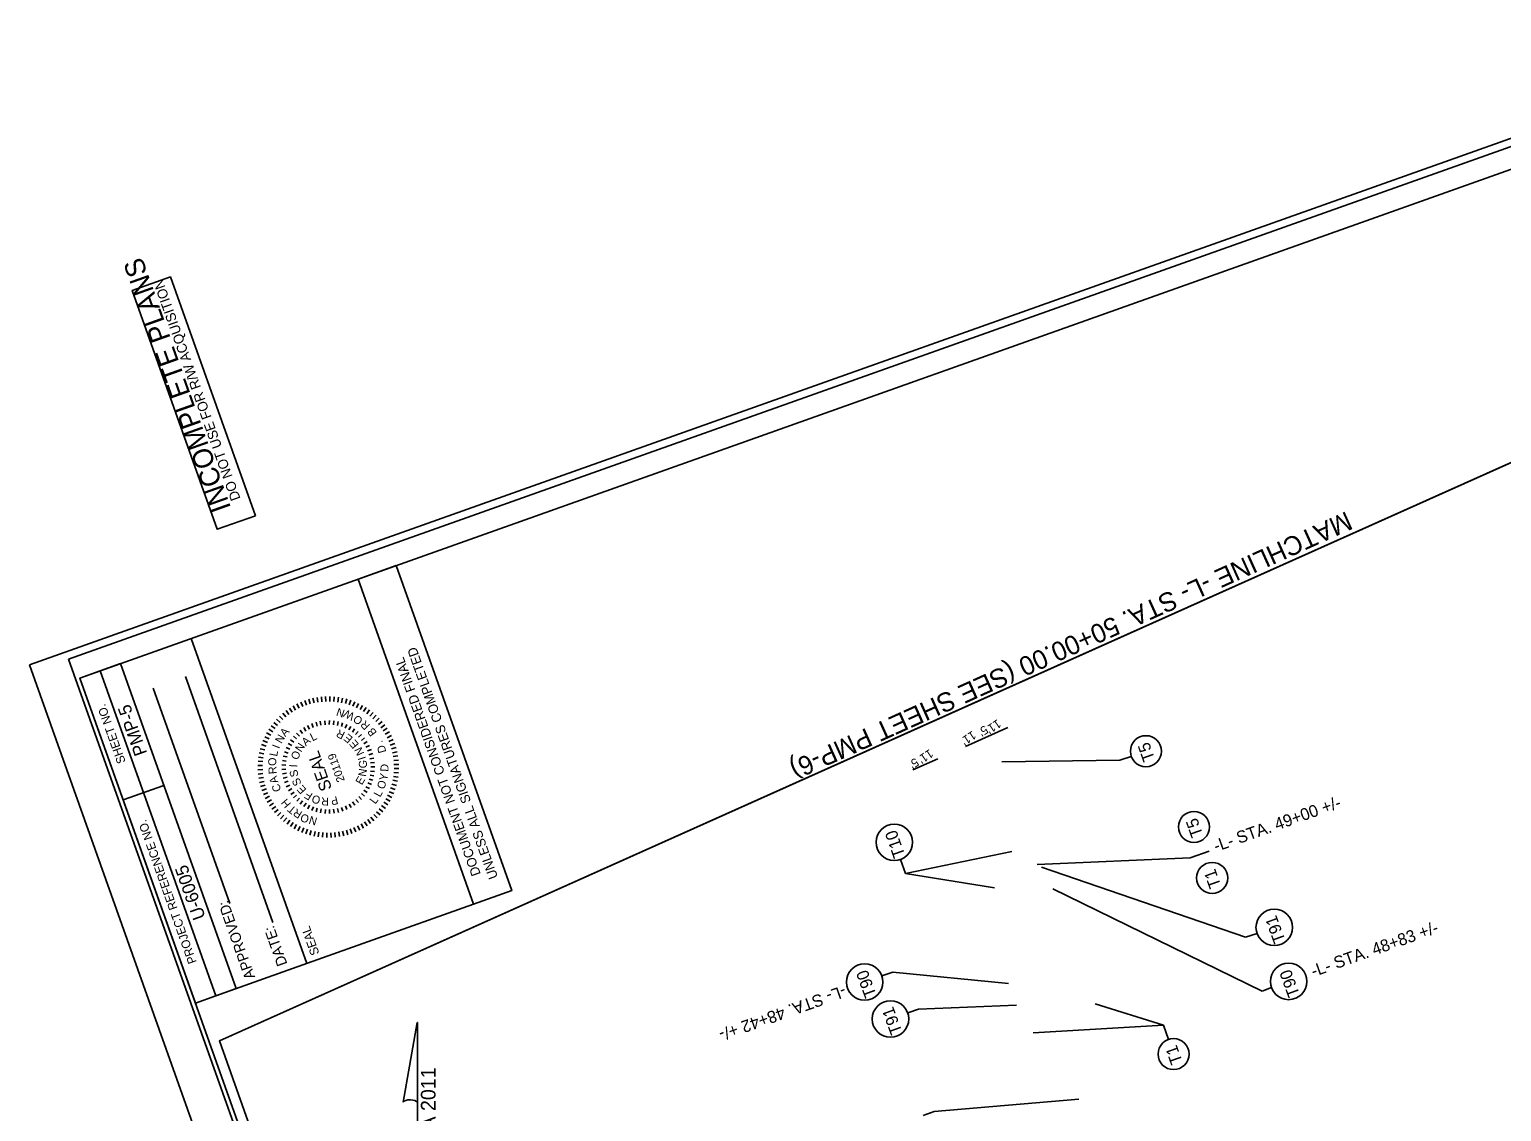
# Model space of a CAD drawing. Extents: x 1615843 to 1617934, y 901966 to 903921.
# Drawn here: x 1615843 to 1616697, y 903293 to 903921 of the extents above; entities that cross this region are included whole.
import ezdxf

# ---------------------------------------------------------------- set-up
doc = ezdxf.new("R2010")
doc.units = 0
for name, color, linetype in [('Matchline', 7, 'Continuous'), ('Matchline Text', 7, 'Continuous'), ('Prop Terminator CELL', 7, 'Continuous'), ('Scratch_Level_0', 7, 'Continuous'), ('Sheet Block Revision CELL', 7, 'Continuous'), ('Sheet Border Standard 30in CELL', 7, 'Continuous'), ('Sheet Clip Boundary CELL', 7, 'Continuous'), ('Sheet Data Field CELL', 7, 'Continuous'), ('Sheet North Arrow Point CELL', 7, 'Continuous'), ('Sheet Plan Layout CELL', 7, 'Continuous'), ('Sheet Plot Border Inside CELL', 7, 'Continuous'), ('Sheet Plot Border Outside CELL', 7, 'Continuous'), ('Sheet Sticker Exception Certification CELL', 7, 'Continuous'), ('Sheet Sticker Incomplete CELL', 7, 'Continuous'), ('Sheet Sticker Preliminary CELL', 7, 'Continuous')]:
    doc.layers.add(name, color=color, linetype=linetype)

msp = doc.modelspace()

# ---------------------------------------------------------------- linework, layer by layer
at = {"layer": 'Matchline'}
msp.add_line((1615953.12, 903334.31), (1616903.33, 903759.78), dxfattribs=at)
at = {"layer": 'Prop Terminator CELL'}
for p, q in [((1616059.69, 903298.71), (1616067.89, 903345.06)), ((1616067.94, 903345.06), (1616067.89, 903345.06)), ((1616067.94, 903345.06), (1616067.89, 903345.06)), ((1616067.94, 903345.06), (1616067.94, 903297.26)), ((1616067.94, 903272.46), (1616067.94, 903298.66)), ((1616067.94, 903297.26), (1616067.94, 903298.61))]:
    msp.add_line(p, q, dxfattribs=at)
msp.add_ellipse((1616063.83, 903298.22), major_axis=(4.23, -0.03), ratio=0.461098, start_param=0.216388, end_param=2.908219, dxfattribs=at)
at = {"layer": 'Sheet Block Revision CELL'}
for p, q in [((1616002.65, 903531.64), (1616003.58, 903529.02)), ((1616005.01, 903532.4), (1616005.78, 903529.72)), ((1616007.4, 903533.01), (1616008.01, 903530.29)), ((1616009.82, 903533.48), (1616010.26, 903530.73)), ((1616012.27, 903533.79), (1616012.55, 903531.02)), ((1616014.73, 903533.96), (1616014.84, 903531.18)), ((1616017.2, 903533.98), (1616017.14, 903531.2)), ((1616019.67, 903533.85), (1616019.44, 903531.08)), ((1616022.12, 903533.58), (1616021.72, 903530.82)), ((1616024.56, 903533.15), (1616023.99, 903530.42)), ((1616026.96, 903532.58), (1616026.23, 903529.89)), ((1616029.32, 903531.87), (1616028.43, 903529.23)), ((1616031.64, 903531.01), (1616030.59, 903528.43)), ((1615988.05, 903522.64), (1615989.97, 903520.63)), ((1615989.88, 903524.3), (1615991.68, 903522.17)), ((1615991.81, 903525.84), (1615993.48, 903523.6)), ((1615993.83, 903527.26), (1615995.36, 903524.93)), ((1615995.93, 903528.55), (1615997.32, 903526.14)), ((1615998.11, 903529.71), (1615999.35, 903527.22)), ((1616000.35, 903530.75), (1616001.44, 903528.18)), ((1616033.89, 903530.01), (1616032.7, 903527.5)), ((1616036.09, 903528.89), (1616034.74, 903526.45)), ((1616038.22, 903527.63), (1616036.72, 903525.28)), ((1616040.26, 903526.24), (1616038.63, 903523.98)), ((1616042.21, 903524.74), (1616040.45, 903522.58)), ((1616044.08, 903523.11), (1616042.18, 903521.07)), ((1615981.8, 903515.02), (1615984.15, 903513.53)), ((1615983.18, 903517.07), (1615985.44, 903515.44)), ((1615984.69, 903519.02), (1615986.85, 903517.26)), ((1615986.31, 903520.89), (1615988.36, 903518.99)), ((1615999.9, 903514.48), (1616001.32, 903512.64)), ((1616002.04, 903515.97), (1616003.27, 903514)), ((1616004.31, 903517.24), (1616005.34, 903515.16)), ((1616006.7, 903518.29), (1616007.53, 903516.12)), ((1616009.17, 903519.09), (1616009.79, 903516.86)), ((1616012.03, 903517.36), (1616011.63, 903519.65)), ((1616014.3, 903519.98), (1616014.47, 903517.67)), ((1616016.9, 903520.05), (1616016.85, 903517.73)), ((1616019.49, 903519.87), (1616019.22, 903517.56)), ((1616022.06, 903519.44), (1616021.57, 903517.17)), ((1616024.58, 903518.76), (1616023.86, 903516.55)), ((1616027.01, 903517.84), (1616026.09, 903515.71)), ((1616029.34, 903516.69), (1616028.22, 903514.66)), ((1616031.56, 903515.32), (1616030.25, 903513.41)), ((1616045.83, 903521.38), (1616043.82, 903519.46)), ((1616047.49, 903519.55), (1616045.36, 903517.74)), ((1616049.03, 903517.62), (1616046.8, 903515.95)), ((1616050.45, 903515.6), (1616048.12, 903514.07)), ((1615977.56, 903506.12), (1615980.2, 903505.24)), ((1615978.42, 903508.44), (1615981, 903507.4)), ((1615979.41, 903510.7), (1615981.92, 903509.5)), ((1615980.54, 903512.9), (1615982.98, 903511.55)), ((1615993.06, 903506.72), (1615995.06, 903505.55)), ((1615994.47, 903508.9), (1615996.36, 903507.54)), ((1615996.1, 903510.93), (1615997.85, 903509.4)), ((1615997.92, 903512.8), (1615999.5, 903511.11)), ((1616033.63, 903513.75), (1616032.14, 903511.97)), ((1616035.54, 903511.98), (1616033.88, 903510.35)), ((1616037.28, 903510.03), (1616035.47, 903508.57)), ((1616038.81, 903507.93), (1616036.87, 903506.65)), ((1616040.13, 903505.69), (1616038.08, 903504.61)), ((1616051.74, 903513.49), (1616049.33, 903512.11)), ((1616052.91, 903511.32), (1616050.41, 903510.08)), ((1616053.94, 903509.08), (1616051.38, 903507.99)), ((1616054.84, 903506.77), (1616052.21, 903505.84)), ((1615975.85, 903498.93), (1615978.61, 903498.53)), ((1615976.27, 903501.36), (1615979, 903500.8)), ((1615976.84, 903503.76), (1615979.53, 903503.04)), ((1615989.64, 903496.95), (1615991.94, 903496.62)), ((1615990.14, 903499.5), (1615992.39, 903498.95)), ((1615990.87, 903502), (1615993.07, 903501.23)), ((1615991.85, 903504.41), (1615993.96, 903503.44)), ((1616041.24, 903503.33), (1616039.09, 903502.46)), ((1616042.11, 903500.88), (1616039.88, 903500.21)), ((1616042.73, 903498.36), (1616040.46, 903497.9)), ((1616055.59, 903504.42), (1616052.91, 903503.65)), ((1616056.2, 903502.03), (1616053.48, 903501.42)), ((1616056.67, 903499.61), (1616053.92, 903499.16)), ((1616056.99, 903497.16), (1616054.21, 903496.88)), ((1615975.44, 903494.01), (1615978.23, 903493.95)), ((1615975.46, 903491.54), (1615978.25, 903491.65)), ((1615975.58, 903496.47), (1615978.35, 903496.25)), ((1615975.63, 903489.07), (1615978.4, 903489.35)), ((1615989.4, 903494.36), (1615991.72, 903494.25)), ((1615989.4, 903491.75), (1615991.72, 903491.87)), ((1615989.66, 903489.16), (1615991.96, 903489.51)), ((1616042.76, 903488), (1616040.48, 903488.44)), ((1616040.81, 903495.54), (1616043.12, 903495.76)), ((1616043.13, 903490.58), (1616040.81, 903490.8)), ((1616043.25, 903493.18), (1616040.92, 903493.18)), ((1616057.04, 903489.76), (1616054.27, 903489.99)), ((1616057.16, 903494.69), (1616054.37, 903494.58)), ((1616057.18, 903492.23), (1616054.39, 903492.29)), ((1615975.95, 903486.63), (1615978.7, 903487.07)), ((1615976.42, 903484.21), (1615979.13, 903484.81)), ((1615977.03, 903481.81), (1615979.7, 903482.58)), ((1615977.78, 903479.46), (1615980.41, 903480.39)), ((1615990.17, 903486.61), (1615992.42, 903487.17)), ((1615990.92, 903484.12), (1615993.1, 903484.89)), ((1615993.1, 903484.89), (1615990.92, 903484.12)), ((1615991.91, 903481.71), (1615994.01, 903482.69)), ((1615993.12, 903479.41), (1615995.12, 903480.59)), ((1616038.88, 903478.41), (1616036.93, 903479.68)), ((1616040.19, 903480.65), (1616038.14, 903481.73)), ((1616041.28, 903483.01), (1616039.13, 903483.89)), ((1616042.14, 903485.47), (1616039.92, 903486.13)), ((1616055.06, 903480.11), (1616052.42, 903480.99)), ((1616055.77, 903482.47), (1616053.09, 903483.2)), ((1616056.35, 903484.87), (1616053.62, 903485.44)), ((1616056.77, 903487.31), (1616054.01, 903487.7)), ((1615978.68, 903477.16), (1615981.24, 903478.24)), ((1615979.71, 903474.92), (1615982.2, 903476.15)), ((1615980.87, 903472.74), (1615983.29, 903474.13)), ((1615982.17, 903470.64), (1615984.5, 903472.17)), ((1615994.55, 903477.23), (1615996.43, 903478.6)), ((1615996.18, 903475.2), (1615997.92, 903476.75)), ((1615998.01, 903473.35), (1615999.59, 903475.05)), ((1616000, 903471.67), (1616001.41, 903473.52)), ((1616002.15, 903470.2), (1616003.37, 903472.18)), ((1616029.46, 903469.6), (1616028.32, 903471.63)), ((1616031.67, 903470.98), (1616030.34, 903472.89)), ((1616033.73, 903472.57), (1616032.23, 903474.34)), ((1616035.63, 903474.35), (1616033.96, 903475.96)), ((1616037.35, 903476.29), (1616035.54, 903477.75)), ((1616050.82, 903471.21), (1616048.47, 903472.7)), ((1616052.08, 903473.34), (1616049.64, 903474.68)), ((1616053.21, 903475.53), (1616050.69, 903476.73)), ((1616054.2, 903477.79), (1616051.62, 903478.84)), ((1615983.59, 903468.61), (1615985.82, 903470.29)), ((1615985.13, 903466.69), (1615987.25, 903468.49)), ((1615986.78, 903464.85), (1615988.8, 903466.78)), ((1615988.54, 903463.12), (1615990.43, 903465.17)), ((1615990.4, 903461.5), (1615992.17, 903463.65)), ((1616004.43, 903468.94), (1616005.45, 903471.03)), ((1616006.81, 903467.91), (1616007.63, 903470.08)), ((1616009.29, 903467.1), (1616009.9, 903469.35)), ((1616011.83, 903466.55), (1616012.22, 903468.84)), ((1616014.42, 903466.24), (1616014.58, 903468.56)), ((1616017.02, 903466.19), (1616016.96, 903468.51)), ((1616019.62, 903466.38), (1616019.33, 903468.69)), ((1616022.18, 903466.83), (1616021.68, 903469.09)), ((1616024.69, 903467.51), (1616023.97, 903469.72)), ((1616027.13, 903468.44), (1616026.2, 903470.57)), ((1616040.81, 903460.4), (1616039.14, 903462.63)), ((1616042.74, 903461.93), (1616040.94, 903464.06)), ((1616044.57, 903463.59), (1616042.65, 903465.6)), ((1616046.31, 903465.35), (1616044.26, 903467.24)), ((1616047.93, 903467.21), (1616045.77, 903468.98)), ((1616049.43, 903469.17), (1616047.18, 903470.8)), ((1615992.36, 903459.99), (1615993.99, 903462.25)), ((1615994.4, 903458.61), (1615995.9, 903460.96)), ((1615996.53, 903457.35), (1615997.88, 903459.78)), ((1615998.72, 903456.22), (1615999.92, 903458.73)), ((1616000.98, 903455.22), (1616002.03, 903457.81)), ((1616003.3, 903454.37), (1616004.19, 903457.01)), ((1616005.66, 903453.65), (1616006.39, 903456.34)), ((1616008.06, 903453.08), (1616008.63, 903455.81)), ((1616010.5, 903452.66), (1616010.89, 903455.42)), ((1616012.95, 903452.38), (1616013.18, 903455.16)), ((1616015.42, 903452.25), (1616015.48, 903455.04)), ((1616017.88, 903452.27), (1616017.77, 903455.06)), ((1616020.35, 903452.44), (1616020.07, 903455.21)), ((1616022.8, 903452.76), (1616022.35, 903455.51)), ((1616025.22, 903453.23), (1616024.61, 903455.94)), ((1616027.61, 903453.84), (1616026.84, 903456.51)), ((1616029.97, 903454.59), (1616029.03, 903457.22)), ((1616032.27, 903455.49), (1616031.18, 903458.05)), ((1616034.51, 903456.52), (1616033.27, 903459.01)), ((1616036.69, 903457.68), (1616035.3, 903460.1)), ((1616038.79, 903458.98), (1616037.26, 903461.3))]:
    msp.add_line(p, q, dxfattribs=at)
at = {"layer": 'Sheet Border Standard 30in CELL'}
for p, q in [((1615951.11, 903360.45), (1615884.09, 903548.94)), ((1615962.88, 903364.63), (1615895.87, 903553.13)), ((1615962.88, 903364.63), (1615895.87, 903553.13)), ((1615897.44, 903474.09), (1615921, 903482.46))]:
    msp.add_line(p, q, dxfattribs=at)
for points in [[(1615872.27, 903544.74), (1616374.72, 902131.39), (1617364.06, 902483.11), (1616861.61, 903896.45)], [(1615939.28, 903356.24), (1615872.27, 903544.74), (1615895.87, 903553.13), (1615962.88, 903364.63)]]:
    msp.add_lwpolyline(points, close=True, dxfattribs=at)
at = {"layer": 'Sheet Clip Boundary CELL'}
for p, q in [((1616410.35, 903516.09), (1616385.7, 903505.08)), ((1616369.73, 903497.94), (1616355.12, 903491.41)), ((1616406.85, 903496.18), (1616475.15, 903497.09)), ((1616475.15, 903497.09), (1616481.82, 903499.29)), ((1616347.97, 903439.52), (1616350.88, 903431.32)), ((1616412.63, 903444.14), (1616350.88, 903431.32)), ((1616412.63, 903444.14), (1616350.88, 903431.32)), ((1616427.35, 903436.64), (1616515.95, 903440.41)), ((1616526.9, 903444.3), (1616515.95, 903440.41)), ((1616402.58, 903423.11), (1616350.88, 903431.32)), ((1616429.84, 903435), (1616548.07, 903394.39)), ((1616436.29, 903422.47), (1616557.64, 903363.25)), ((1616548.07, 903394.39), (1616554.75, 903396.59)), ((1616343.54, 903374.23), (1616337.21, 903371.98)), ((1616410.71, 903367.51), (1616343.54, 903374.23)), ((1616557.64, 903363.25), (1616563.09, 903365.25)), ((1616358.52, 903352.81), (1616352.19, 903350.56)), ((1616415.35, 903355.12), (1616358.52, 903352.81)), ((1616460.8, 903355.84), (1616500.42, 903343.37)), ((1616424.97, 903338.99), (1616500.42, 903343.37)), ((1616503.34, 903335.18), (1616500.42, 903343.37)), ((1616451.42, 903300.58), (1616367.56, 903293.34)), ((1616367.56, 903293.34), (1616361.23, 903291.09))]:
    msp.add_line(p, q, dxfattribs=at)
for centre, radius in [((1616490.31, 903502.3), 9.01), ((1616518.19, 903458.36), 9.01), ((1616344.43, 903449.48), 10.58), ((1616528.71, 903428.79), 9.01), ((1616564.72, 903400.14), 10.58), ((1616327.25, 903368.43), 10.58), ((1616573.06, 903368.79), 10.58), ((1616342.22, 903347.02), 10.58), ((1616506.35, 903326.69), 9.01)]:
    msp.add_circle(centre, radius, dxfattribs=at)
at = {"layer": 'Sheet North Arrow Point CELL'}
for p, q in [((1616033.51, 903602.06), (1616100.52, 903413.57)), ((1616003.8, 903379.18), (1615936.79, 903567.67)), ((1616100.52, 903413.57), (1615995.56, 903376.25)), ((1615995.56, 903376.25), (1615951.11, 903360.45))]:
    msp.add_line(p, q, dxfattribs=at)
at = {"layer": 'Sheet Plan Layout CELL'}
for p, q in [((1615984.13, 903402.97), (1615933.46, 903545.53)), ((1615959.12, 903413.91), (1615914.7, 903538.86))]:
    msp.add_line(p, q, dxfattribs=at)
at = {"layer": 'Sheet Plot Border Inside CELL'}
msp.add_lwpolyline([(1615865.68, 903555.66), (1616423.91, 901985.43), (1617418.05, 902338.86), (1616859.83, 903909.09)], close=True, dxfattribs=at)
at = {"layer": 'Sheet Plot Border Outside CELL'}
msp.add_lwpolyline([(1615843.02, 903552.38), (1616407.11, 901965.67), (1617443.56, 902334.13), (1616879.47, 903920.85)], close=True, dxfattribs=at)
at = {"layer": 'Sheet Sticker Exception Certification CELL'}
msp.add_lwpolyline([(1616100.52, 903413.57), (1616033.51, 903602.06), (1616055.65, 903609.93), (1616122.66, 903421.44)], close=True, dxfattribs=at)
at = {"layer": 'Sheet Sticker Incomplete CELL'}
msp.add_lwpolyline([(1616920.55, 902382.99), (1616299.46, 902356.07), (1615953.12, 903334.31), (1616369.18, 903520.6), (1616903.33, 903759.78), (1617120.19, 903154.34), (1616822.61, 903059.96), (1617083.45, 902390.05)], close=True, dxfattribs=at)
at = {"layer": 'Sheet Sticker Preliminary CELL'}
msp.add_lwpolyline([(1615974.04, 903638.86), (1615951.9, 903630.98), (1615902.66, 903769.49), (1615924.8, 903777.36)], close=True, dxfattribs=at)

# ---------------------------------------------------------------- texts
at = {"layer": 'Matchline Text'}
msp.add_text('MATCHLINE -L- STA. 50+00.00 (SEE SHEET PMP-6)', height=11, rotation=204.28176, dxfattribs=at).set_placement((1616606.6, 903641.67))
at = {"layer": 'Prop Terminator CELL'}
msp.add_text('NAD 83/NA 2011', height=8.5, rotation=90, dxfattribs=at).set_placement((1616078.46, 903231.75))
at = {"layer": 'Scratch_Level_0'}
for s, p in [('APPROVED:', (1615973.98, 903371.32)), ('DATE:', (1615992.65, 903378.94))]:
    msp.add_text(s, height=6.11, rotation=109.56562, dxfattribs=at).set_placement(p)
at = {"layer": 'Sheet Block Revision CELL'}
for s, height, rotation, p in [('N', 4.64, 161.72472, (1616026.23, 903526.09)), ('W', 4.64, 152.84209, (1616031.93, 903523.98)), ('O', 4.64, 143.95946, (1616036.74, 903520.84)), ('A', 4.64, 50.03476, (1615991.35, 903510.39)), ('R', 4.64, 154.08255, (1616026.36, 903513.17)), ('R', 4.64, 135.13685, (1616040.89, 903517.42)), ('B', 4.64, 126.13428, (1616044.66, 903513.07)), ('I', 4.64, 69.09675, (1615987.86, 903503.44)), ('N', 4.64, 59.80229, (1615989.15, 903506.36)), ('N', 4.64, 55.9808, (1616000.53, 903501.38)), ('A', 4.64, 40.68456, (1616003.26, 903505.04)), ('L', 4.64, 25.38831, (1616007.09, 903507.99)), ('E', 4.64, 140.31147, (1616030.88, 903510.08)), ('E', 4.64, 130.32559, (1616034.34, 903506.26)), ('D', 4.64, 105.60762, (1616049.99, 903501.94)), ('.', 4.64, 113.34997, (1616048.07, 903507.46)), ('O', 4.64, 91.80851, (1615986.2, 903493.87)), ('L', 4.64, 78.67223, (1615986.57, 903499.01)), ('O', 4.64, 71.27705, (1615998.8, 903496.97)), ('SEAL', 6.965, 109.51767, (1616018.51, 903480.66)), ('20119', 4.64, 109.51767, (1616025.92, 903485.3)), ('N', 4.64, 114.93352, (1616037.28, 903501.06)), ('I', 4.64, 107.30386, (1616038.19, 903498.04)), ('G', 4.64, 89.20906, (1616038.63, 903492.34)), ('R', 4.64, 94.86532, (1615986.45, 903489.19)), ('A', 4.64, 106.87463, (1615987.44, 903484.33)), ('I', 4.64, 86.5733, (1615998.34, 903492.84)), ('S', 4.64, 101.86954, (1615999.05, 903487.85)), ('N', 4.64, 80.44283, (1616038.1, 903487.33)), ('Y', 4.64, 78.83983, (1616050.24, 903484.93)), ('D', 4.64, 87.81231, (1616051.1, 903490.36)), ('C', 4.64, 106.87463, (1615989.05, 903479.52)), ('S', 4.64, 117.16579, (1616000.96, 903483.61)), ('E', 4.64, 132.46203, (1616003.92, 903480.04)), ('E', 4.64, 59.58776, (1616035.75, 903482.37)), ('O', 4.64, 70.16724, (1616048.61, 903479.87)), ('H', 4.64, 130.58532, (1615994.94, 903471.81)), ('F', 4.64, 147.75828, (1616007.63, 903477.42)), ('O', 4.64, 163.05453, (1616012.19, 903475.76)), ('R', 4.64, 178.35077, (1616016.73, 903475.42)), ('P', 4.64, 193.64702, (1616021.3, 903476.3)), ('L', 4.64, 53.45268, (1616043.54, 903471.29)), ('L', 4.64, 61.52449, (1616046.34, 903475.33)), ('T', 4.64, 140.01727, (1615998.1, 903468.96)), ('R', 4.64, 148.17823, (1616001.59, 903466.89)), ('O', 4.64, 161.23496, (1616005.66, 903464.77)), ('N', 4.64, 163.19439, (1616010.24, 903463.56))]:
    msp.add_text(s, height=height, rotation=rotation, dxfattribs=at).set_placement(p)
at = {"layer": 'Sheet Border Standard 30in CELL'}
for s, height, p in [('SHEET NO.', 5, (1615898.88, 903496.14)), ('PROJECT REFERENCE NO.', 5.0001, (1615940.04, 903380.07))]:
    msp.add_text(s, height=height, rotation=109.57069, dxfattribs=at).set_placement(p)
at = {"layer": 'Sheet Clip Boundary CELL'}
for s, height, rotation, p in [("11'", 5, 214.18634, (1616389.71, 903514.38)), ("5'", 5, 214.18634, (1616396.73, 903517.51)), ("11'", 5, 214.18634, (1616404.22, 903521.06)), ('T5', 7, 109.53987, (1616495.63, 903497.79)), ("5'", 5, 214.18634, (1616356.51, 903498.69)), ("11'", 5, 214.18634, (1616364.88, 903503.77)), ('-L- STA. 49+00 +/-', 7, 19.57069, (1616531.04, 903443.81)), ('T5', 7, 109.53987, (1616523.51, 903453.84)), ('T10', 7, 109.57069, (1616350.86, 903441.95)), ('T1', 7, 109.53987, (1616534.02, 903424.27)), ('T91', 7, 110.1663, (1616571.35, 903392.53)), ('-L- STA. 48+83 +/-', 7, 19.57069, (1616587.48, 903371.27)), ('T90', 7, 110.1663, (1616334.25, 903360.94)), ('T90', 7, 110.1663, (1616579.7, 903361.19)), ('-L- STA. 48+42 +/-', 7, 199.57069, (1616315.04, 903366.73)), ('T91', 7, 110.1663, (1616349.22, 903339.53)), ('T1', 7, 109.53987, (1616511.67, 903322.18))]:
    msp.add_text(s, height=height, rotation=rotation, dxfattribs=at).set_placement(p)
at = {"layer": 'Sheet Data Field CELL'}
for s, p in [('PMP-5', (1615911.36, 903501.2)), ('U-6005', (1615945.24, 903406.05))]:
    msp.add_text(s, height=7.5, rotation=109.57069, dxfattribs=at).set_placement(p)
at = {"layer": 'Sheet Plan Layout CELL'}
msp.add_text('SEAL', height=5.094, rotation=109.56562, dxfattribs=at).set_placement((1616011.18, 903385.01))
at = {"layer": 'Sheet Sticker Exception Certification CELL'}
for s, p in [('DOCUMENT NOT CONSIDERED FINAL', (1616104.76, 903431.07)), ('UNLESS ALL SIGNATURES COMPLETED', (1616114.74, 903429.24))]:
    msp.add_text(s, height=5.4984, rotation=109.57069, dxfattribs=at).set_placement(p)
at = {"layer": 'Sheet Sticker Preliminary CELL'}
for s, height, p in [('INCOMPLETE PLANS', 11.52, (1615960.02, 903643.37)), ('DO NOT USE FOR R/W ACQUISITION', 5.76, (1615965.48, 903648.76))]:
    msp.add_text(s, height=height, rotation=109.57069, dxfattribs=at).set_placement(p)

doc.saveas('drawing.dxf')
